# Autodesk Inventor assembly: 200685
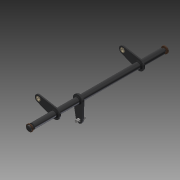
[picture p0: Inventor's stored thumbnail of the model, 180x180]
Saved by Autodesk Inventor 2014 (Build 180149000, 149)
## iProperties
Created: 2007-12
Part Number: 200685
Document SubType Name: Assembly
Designer: MM
Mass: 762.988 g
Surface Area: 385.242 cm^2
Volume: 97.3962 cm^3
Density: 7.83386 g/cm^3
Description: PIVOT LINK WELDMENT
Component Category: Lower Component
Author: MM
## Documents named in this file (5)
- C:\Users\iTools\Desktop\tutorial files\Automotive\2000\200685.iam
- C:\Users\iTools\Desktop\tutorial files\Automotive\2000\201681.iam
- C:\Users\iTools\Desktop\tutorial files\Automotive\8000\800587.ipt
- C:\Users\iTools\Desktop\tutorial files\Automotive\8000\800391.ipt
- C:\Users\iTools\Desktop\tutorial files\Automotive\8000\800463.ipt
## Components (6 placed, 4 different names)
1. 201681:1 [sub-assembly] — Insert:1, Insert:2, Angle:1, Angle:2, Insert:3, Insert:4, Insert:5
2. 800587:1 — Insert:1, Angle:2
3. 800587:2 — Insert:2, Angle:1
4. 800391:1 — Insert:3
5. 800391:2 — Insert:4
6. 800463:1 — Insert:5
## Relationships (7: Insert 5, Angle 2)
- Insert:1: 201681:1 ↔ 800587:1
- Insert:2: 201681:1 ↔ 800587:2
- Angle:1: 201681:1 ↔ 800587:2
- Angle:2: 201681:1 ↔ 800587:1
- Insert:3: 201681:1 ↔ 800391:1
- Insert:4: 201681:1 ↔ 800391:2
- Insert:5: 201681:1 ↔ 800463:1
